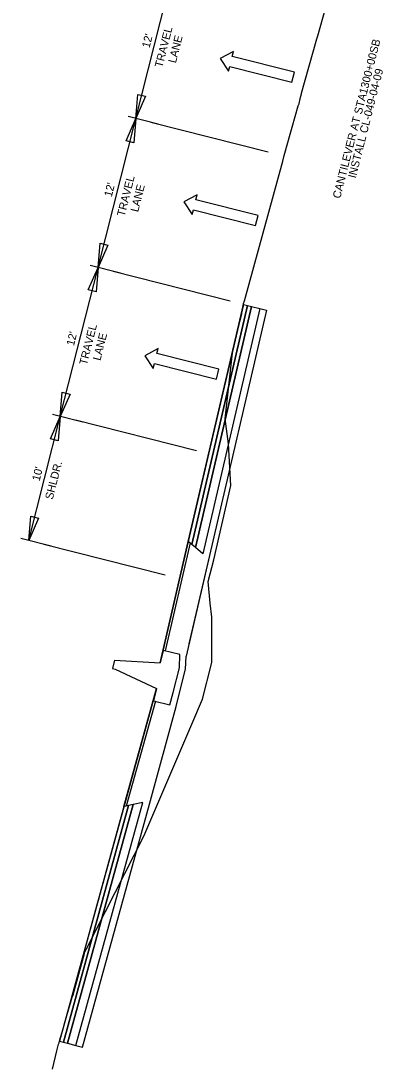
# Model space of a CAD drawing. Extents: x 670002 to 670131, y 737831 to 738002.
# Drawn here: x 670080.1 to 670108.4, y 737831 to 737912.9 of the extents above; entities that cross this region are included whole.
import ezdxf

# ---------------------------------------------------------------- set-up
doc = ezdxf.new("R2010")
doc.units = 0
for name, color, linetype in [('R_Alt Surface', 7, 'Continuous'), ('R_Exist Surface', 7, 'Continuous'), ('R_Fin Surface', 7, 'Continuous'), ('R_MOT', 7, 'Continuous'), ('R_SIGN_ANNOT', 7, 'Continuous')]:
    doc.layers.add(name, color=color, linetype=linetype)

msp = doc.modelspace()

# ---------------------------------------------------------------- linework, layer by layer
for points in [[(670090.716, 737860.782), (670090.47, 737859.812), (670091.763, 737859.485), (670092.009, 737860.454), (670092.5, 737862.393), (670092.532, 737863.416), (670091.239, 737863.744), (670090.993, 737862.775)], [(670087.436, 737862.986), (670087.436, 737862.986), (670087.274, 737862.346), (670087.488, 737862.292)], [(670087.436, 737862.986), (670090.993, 737862.775)], [(670087.488, 737862.292), (670090.716, 737860.782)]]:
    msp.add_lwpolyline(points)
at = {"layer": 'R_Alt Surface'}
for points in [[(670098.788, 737890.449), (670099.313, 737890.316), (670094.854, 737871.156), (670093.024, 737863.291)], [(670098.788, 737890.449), (670099.313, 737890.316), (670094.854, 737871.156), (670093.251, 737864.266)], [(670092.255, 737859.36), (670092.493, 737860.331), (670092.985, 737862.27), (670093.024, 737863.291)], [(670084.422, 737832.893), (670084.947, 737832.76), (670090.159, 737851.729), (670092.255, 737859.36)]]:
    msp.add_lwpolyline(points, dxfattribs=at)
for points in [[(670097.822, 737890.694), (670098.142, 737890.613), (670093.764, 737871.778), (670093.482, 737872.022)], [(670098.142, 737890.613), (670098.788, 737890.449), (670094.331, 737871.289), (670093.764, 737871.778)], [(670083.456, 737833.138), (670083.776, 737833.057), (670088.904, 737851.702), (670088.539, 737851.622)], [(670083.776, 737833.057), (670084.422, 737832.893), (670089.635, 737851.862), (670088.904, 737851.702)]]:
    msp.add_lwpolyline(points, close=True, dxfattribs=at)
at = {"layer": 'R_Exist Surface'}
msp.add_lwpolyline([(670082.602, 737831.048), (670082.946, 737832.476), (670083.076, 737833.003), (670083.086, 737833.036), (670083.105, 737833.094), (670083.208, 737833.432), (670083.411, 737834.076), (670083.547, 737834.602), (670083.835, 737835.666), (670083.997, 737836.185), (670084.137, 737836.655), (670084.182, 737836.77), (670084.217, 737836.841), (670085.095, 737840.066), (670085.122, 737840.166), (670085.249, 737840.431), (670089.715, 737849.23), (670093.539, 737858.163), (670094.313, 737859.939), (670095.003, 737862.691), (670095.037, 737862.83), (670095.045, 737862.877), (670095.031, 737866.351), (670094.908, 737867.436), (670094.747, 737869.123), (670095.192, 737870.818), (670096.529, 737876.628), (670096.324, 737879.892), (670096.075, 737881.844), (670096.601, 737886.523), (670096.647, 737886.936), (670096.647, 737886.946), (670096.655, 737886.978), (670097.026, 737888.651), (670097.047, 737888.741), (670097.368, 737890.043), (670097.373, 737890.071), (670097.491, 737890.719), (670097.512, 737890.827), (670097.515, 737890.84), (670097.572, 737891.052), (670100.562, 737901.954), (670100.683, 737902.394), (670101.191, 737904.241), (670101.309, 737904.607), (670101.769, 737906.269), (670101.851, 737906.445), (670101.855, 737906.453), (670101.916, 737906.833), (670101.921, 737906.858), (670102.027, 737907.226), (670102.031, 737907.233), (670102.041, 737907.274), (670103.233, 737911.517), (670103.295, 737911.737), (670103.909, 737913.894)], dxfattribs=at)
at = {"layer": 'R_Fin Surface'}
for points in [[(670097.502, 737890.775), (670094.785, 737879.085), (670092.52, 737869.342), (670090.993, 737862.775)], [(670093.341, 737872.143), (670091.401, 737863.703), (670091.239, 737863.744), (670090.993, 737862.775), (670093.199, 737872.265), (670093.341, 737872.143)], [(670090.716, 737860.782), (670088.971, 737854.436), (670086.319, 737844.792), (670083.136, 737833.219)], [(670088.175, 737851.542), (670090.716, 737860.782), (670090.47, 737859.812), (670090.632, 737859.771), (670088.357, 737851.582), (670088.175, 737851.542)]]:
    msp.add_lwpolyline(points, dxfattribs=at)
for points in [[(670097.502, 737890.775), (670097.822, 737890.694), (670093.482, 737872.022), (670093.199, 737872.265)], [(670083.136, 737833.219), (670083.456, 737833.138), (670088.539, 737851.622), (670088.175, 737851.542)]]:
    msp.add_lwpolyline(points, close=True, dxfattribs=at)
at = {"layer": 'R_MOT'}
for p, q in [((670096.732, 737910.528), (670095.685, 737909.968)), ((670096.633, 737910.14), (670096.732, 737910.528)), ((670095.685, 737909.968), (670096.338, 737908.977)), ((670101.476, 737908.912), (670096.633, 737910.14)), ((670096.338, 737908.977), (670096.437, 737909.365)), ((670096.437, 737909.365), (670101.279, 737908.137)), ((670101.279, 737908.137), (670101.476, 737908.912)), ((670093.893, 737899.335), (670092.846, 737898.775)), ((670093.794, 737898.947), (670093.893, 737899.335)), ((670098.637, 737897.719), (670093.794, 737898.947)), ((670092.846, 737898.775), (670093.499, 737897.784)), ((670093.499, 737897.784), (670093.598, 737898.171)), ((670093.598, 737898.171), (670098.44, 737896.943)), ((670098.44, 737896.943), (670098.637, 737897.719)), ((670090.847, 737887.327), (670089.8, 737886.767)), ((670089.8, 737886.767), (670090.454, 737885.776)), ((670090.749, 737886.939), (670090.847, 737887.327)), ((670095.591, 737885.711), (670090.749, 737886.939)), ((670090.454, 737885.776), (670090.552, 737886.163)), ((670090.552, 737886.163), (670095.395, 737884.935)), ((670095.395, 737884.935), (670095.591, 737885.711))]:
    msp.add_line(p, q, dxfattribs=at)
at = {"layer": 'R_SIGN_ANNOT'}
for p, q in [((670089.101, 737905.286), (670092.052, 737916.918)), ((670086.151, 737893.654), (670089.101, 737905.286)), ((670090.852, 737904.842), (670088.496, 737905.44)), ((670099.42, 737902.669), (670090.283, 737904.986)), ((670083.201, 737882.022), (670086.151, 737893.654)), ((670087.902, 737893.21), (670085.546, 737893.808)), ((670096.47, 737891.037), (670087.333, 737893.354)), ((670080.743, 737872.329), (670083.201, 737882.022)), ((670084.952, 737881.578), (670082.596, 737882.176)), ((670093.847, 737879.322), (670084.383, 737881.723)), ((670082.494, 737871.885), (670080.137, 737872.483)), ((670091.389, 737869.629), (670081.925, 737872.03))]:
    msp.add_line(p, q, dxfattribs=at)
for points in [[(670089.865, 737907.027), (670089.101, 737905.286), (670089.26, 737907.18)], [(670088.338, 737903.545), (670089.101, 737905.286), (670088.943, 737903.392)], [(670086.915, 737895.395), (670086.151, 737893.654), (670086.309, 737895.548)], [(670085.388, 737891.914), (670086.151, 737893.654), (670085.993, 737891.76)], [(670083.965, 737883.763), (670083.201, 737882.022), (670083.359, 737883.917)], [(670082.437, 737880.282), (670083.201, 737882.022), (670083.043, 737880.128)], [(670081.507, 737874.07), (670080.743, 737872.329), (670080.901, 737874.224)]]:
    msp.add_lwpolyline(points, close=True, dxfattribs=at)

# ---------------------------------------------------------------- texts
for s, p in [('TRAVEL', (670091.17, 737909.23)), ("12'", (670090.167, 737910.759)), ('LANE', (670092.225, 737909.577)), ('CANTILEVER AT STA1300+00SB', (670105.054, 737899.001)), ('INSTALL CL-049-04-09', (670106.264, 737900.588)), ('TRAVEL', (670088.22, 737897.599)), ("12'", (670087.217, 737899.127)), ('LANE', (670089.275, 737897.945)), ('TRAVEL', (670085.277, 737885.994)), ("12'", (670084.267, 737887.495)), ('LANE', (670086.332, 737886.34)), ("10'", (670081.589, 737876.935)), ('SHLDR.', (670082.612, 737875.487))]:
    msp.add_text(s, height=0.625, rotation=75.76855, dxfattribs=at).set_placement(p)

doc.saveas('drawing.dxf')
